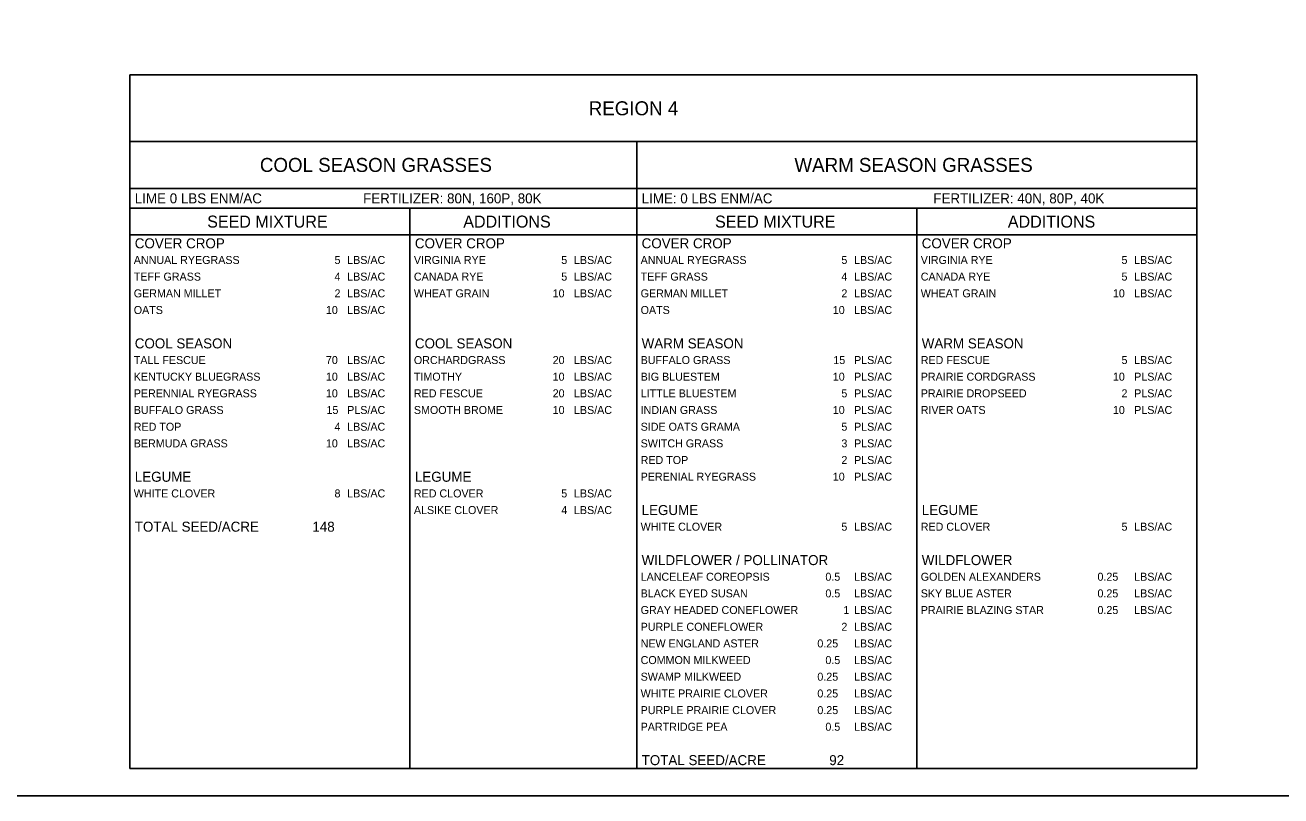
# Model space of a CAD drawing. Extents: x 0 to 3125, y 0 to 2037.
# Drawn here: x 1074 to 2214, y 0 to 699 of the extents above; entities that cross this region are included whole.
import ezdxf

# ---------------------------------------------------------------- set-up
doc = ezdxf.new("R2010")
doc.units = 0
for name, color, linetype in [('Common-Notes', 7, 'Continuous'), ('Draft_Named_Boundary', 7, 'Continuous'), ('Grid_Line-Main', 7, 'Continuous')]:
    doc.layers.add(name, color=color, linetype=linetype)

msp = doc.modelspace()

# ---------------------------------------------------------------- linework, layer by layer
at = {"layer": 'Draft_Named_Boundary'}
msp.add_lwpolyline([(0, 0), (3125, 0), (3125, 2037.5), (0, 2037.5)], close=True, dxfattribs=at)
at = {"layer": 'Grid_Line-Main'}
for p, q in [((1169.4, 654.1), (2137.4, 654.1)), ((1169.4, 654.1), (1169.4, 24.9)), ((2137.4, 654.1), (2137.4, 24.9)), ((1169.4, 593.6), (2137.4, 593.6)), ((1629.2, 593.6), (1629.2, 24.9)), ((1169.4, 551.2), (2137.4, 551.2)), ((1169.4, 533.1), (2137.4, 533.1)), ((1423.5, 533.1), (1423.5, 24.9)), ((1883.3, 533.1), (1883.3, 24.9)), ((1169.4, 508.9), (2137.4, 508.9)), ((1169.4, 24.9), (2137.4, 24.9))]:
    msp.add_line(p, q, dxfattribs=at)

# ---------------------------------------------------------------- texts
at = {"layer": 'Common-Notes'}
for s, height, p in [(' REGION 4', 12.7, (1581, 617.5)), ('COOL SEASON GRASSES', 12.705, (1287.4, 566.1)), ('WARM SEASON GRASSES', 12.705, (1772.3, 566.1)), ('LIME 0 LBS ENM/AC', 9.075, (1173.9, 537.6)), ('FERTILIZER: 80N, 160P, 80K', 9.075, (1381, 537.6)), ('LIME: 0 LBS ENM/AC', 9.075, (1633.7, 537.6)), ('FERTILIZER: 40N, 80P, 40K', 9.075, (1898.3, 537.6)), ('SEED MIXTURE', 10.89, (1239.6, 515.6)), ('ADDITIONS ', 10.89, (1471.9, 515.6)), ('SEED MIXTURE', 10.89, (1700.3, 515.6)), ('ADDITIONS ', 10.89, (1965.9, 515.6)), ('COVER CROP', 9.08, (1173.9, 496.8)), ('COVER CROP', 9.08, (1428, 496.8)), ('COVER CROP', 9.08, (1633.7, 496.8)), ('COVER CROP', 9.08, (1887.8, 496.8)), ('ANNUAL RYEGRASS', 7.26, (1173, 482.6)), ('5', 7.26, (1355.1, 482.6)), ('LBS/AC', 7.26, (1366.6, 482.6)), ('VIRGINIA RYE', 7.26, (1427.1, 482.6)), ('5', 7.26, (1560.8, 482.6)), ('LBS/AC', 7.26, (1572.3, 482.6)), ('ANNUAL RYEGRASS', 7.26, (1632.8, 482.6)), ('5', 7.26, (1814.9, 482.6)), ('LBS/AC', 7.26, (1826.4, 482.6)), ('VIRGINIA RYE', 7.26, (1886.9, 482.6)), ('5', 7.26, (2069, 482.6)), ('LBS/AC', 7.26, (2080.5, 482.6)), ('TEFF GRASS', 7.26, (1173, 467.5)), ('4', 7.26, (1355.1, 467.5)), ('LBS/AC', 7.26, (1366.6, 467.5)), ('CANADA RYE', 7.26, (1427.1, 467.5)), ('5', 7.26, (1560.8, 467.5)), ('LBS/AC', 7.26, (1572.3, 467.5)), ('TEFF GRASS', 7.26, (1632.8, 467.5)), ('4', 7.26, (1814.9, 467.5)), ('LBS/AC', 7.26, (1826.4, 467.5)), ('CANADA RYE', 7.26, (1886.9, 467.5)), ('5', 7.26, (2069, 467.5)), ('LBS/AC', 7.26, (2080.5, 467.5)), ('GERMAN MILLET', 7.26, (1173, 452.3)), ('2', 7.26, (1355.1, 452.3)), ('LBS/AC', 7.26, (1366.6, 452.3)), ('WHEAT GRAIN', 7.26, (1427.1, 452.3)), ('10', 7.26, (1553, 452.3)), ('LBS/AC', 7.26, (1572.3, 452.3)), ('GERMAN MILLET', 7.26, (1632.8, 452.3)), ('2', 7.26, (1814.9, 452.3)), ('LBS/AC', 7.26, (1826.4, 452.3)), ('WHEAT GRAIN', 7.26, (1886.9, 452.3)), ('10', 7.26, (2061.2, 452.3)), ('LBS/AC', 7.26, (2080.5, 452.3)), ('OATS', 7.26, (1173, 437.2)), ('10', 7.26, (1347.3, 437.2)), ('LBS/AC', 7.26, (1366.6, 437.2)), ('OATS', 7.26, (1632.8, 437.2)), ('10', 7.26, (1807.1, 437.2)), ('LBS/AC', 7.26, (1826.4, 437.2)), ('COOL SEASON', 9.075, (1173.9, 406)), ('COOL SEASON', 9.075, (1428, 406)), ('WARM SEASON', 9.075, (1633.7, 406)), ('WARM SEASON', 9.075, (1887.8, 406)), ('TALL FESCUE', 7.26, (1173, 391.8)), ('70', 7.26, (1347.3, 391.8)), ('LBS/AC', 7.26, (1366.6, 391.8)), ('ORCHARDGRASS', 7.26, (1427.1, 391.8)), ('20', 7.26, (1553, 391.8)), ('LBS/AC', 7.26, (1572.3, 391.8)), ('BUFFALO GRASS', 7.26, (1632.8, 391.8)), ('15', 7.26, (1807.6, 391.8)), ('PLS/AC', 7.26, (1826.4, 391.8)), ('RED FESCUE', 7.26, (1886.9, 391.8)), ('5', 7.26, (2069, 391.8)), ('LBS/AC', 7.26, (2080.5, 391.8)), ('KENTUCKY BLUEGRASS', 7.26, (1173, 376.7)), ('10', 7.26, (1347.3, 376.7)), ('LBS/AC', 7.26, (1366.6, 376.7)), ('TIMOTHY', 7.26, (1427.1, 376.7)), ('10', 7.26, (1553, 376.7)), ('LBS/AC', 7.26, (1572.3, 376.7)), ('BIG BLUESTEM', 7.26, (1632.8, 376.7)), ('10', 7.26, (1807.1, 376.7)), ('PLS/AC', 7.26, (1826.4, 376.7)), ('PRAIRIE CORDGRASS', 7.26, (1886.9, 376.7)), ('10', 7.26, (2061.2, 376.7)), ('PLS/AC', 7.26, (2080.5, 376.7)), ('PERENNIAL RYEGRASS', 7.26, (1173, 361.6)), ('10', 7.26, (1347.3, 361.6)), ('LBS/AC', 7.26, (1366.6, 361.6)), ('RED FESCUE', 7.26, (1427.1, 361.6)), ('20', 7.26, (1553, 361.6)), ('LBS/AC', 7.26, (1572.3, 361.6)), ('LITTLE BLUESTEM', 7.26, (1632.8, 361.6)), ('5', 7.26, (1814.9, 361.6)), ('PLS/AC', 7.26, (1826.4, 361.6)), ('PRAIRIE DROPSEED', 7.26, (1886.9, 361.6)), ('2', 7.26, (2069, 361.6)), ('PLS/AC', 7.26, (2080.5, 361.6)), ('BUFFALO GRASS', 7.26, (1173, 346.5)), ('15', 7.26, (1347.8, 346.5)), ('PLS/AC', 7.26, (1366.6, 346.5)), ('SMOOTH BROME', 7.26, (1427.1, 346.5)), ('10', 7.26, (1553, 346.5)), ('LBS/AC', 7.26, (1572.3, 346.5)), ('INDIAN GRASS', 7.26, (1632.8, 346.5)), ('10', 7.26, (1807.1, 346.5)), ('PLS/AC', 7.26, (1826.4, 346.5)), ('RIVER OATS', 7.26, (1886.9, 346.5)), ('10', 7.26, (2061.2, 346.5)), ('PLS/AC', 7.26, (2080.5, 346.5)), ('RED TOP', 7.26, (1173, 331.3)), ('4', 7.26, (1355.1, 331.3)), ('LBS/AC', 7.26, (1366.6, 331.3)), ('SIDE OATS GRAMA', 7.26, (1632.8, 331.3)), ('5', 7.26, (1814.9, 331.3)), ('PLS/AC', 7.26, (1826.4, 331.3)), ('BERMUDA GRASS', 7.26, (1173, 316.2)), ('10', 7.26, (1347.3, 316.2)), ('LBS/AC', 7.26, (1366.6, 316.2)), ('SWITCH GRASS', 7.26, (1632.8, 316.2)), ('3', 7.26, (1814.9, 316.2)), ('PLS/AC', 7.26, (1826.4, 316.2)), ('RED TOP', 7.26, (1632.8, 301.1)), ('2', 7.26, (1814.9, 301.1)), ('PLS/AC', 7.26, (1826.4, 301.1)), ('LEGUME', 9.08, (1173.9, 285)), ('LEGUME', 9.08, (1428, 285)), ('PERENIAL RYEGRASS', 7.26, (1632.8, 286)), ('10', 7.26, (1807.1, 286)), ('PLS/AC', 7.26, (1826.4, 286)), ('WHITE CLOVER', 7.26, (1173, 270.8)), ('8', 7.26, (1355.1, 270.8)), ('LBS/AC', 7.26, (1366.6, 270.8)), ('RED CLOVER', 7.26, (1427.1, 270.8)), ('5', 7.26, (1560.8, 270.8)), ('LBS/AC', 7.26, (1572.3, 270.8)), ('ALSIKE CLOVER', 7.26, (1427.1, 255.7)), ('4', 7.26, (1560.8, 255.7)), ('LBS/AC', 7.26, (1572.3, 255.7)), ('LEGUME ', 9.08, (1633.7, 254.8)), ('LEGUME', 9.08, (1887.8, 254.8)), ('TOTAL SEED/ACRE', 9.075, (1173.9, 239.7)), ('148', 9.08, (1335, 239.7)), ('WHITE CLOVER', 7.26, (1632.8, 240.6)), ('5', 7.26, (1814.9, 240.6)), ('LBS/AC', 7.26, (1826.4, 240.6)), ('RED CLOVER', 7.26, (1886.9, 240.6)), ('5', 7.26, (2069, 240.6)), ('LBS/AC', 7.26, (2080.5, 240.6)), ('WILDFLOWER / POLLINATOR ', 9.075, (1633.7, 209.4)), ('WILDFLOWER', 9.08, (1887.8, 209.4)), ('LANCELEAF COREOPSIS', 7.26, (1632.8, 195.2)), ('0.5', 7.26, (1800.4, 195.2)), ('LBS/AC', 7.26, (1826.4, 195.2)), ('GOLDEN ALEXANDERS', 7.26, (1886.9, 195.2)), ('0.25', 7.26, (2047.2, 195.2)), ('LBS/AC', 7.26, (2080.5, 195.2)), ('BLACK EYED SUSAN', 7.26, (1632.8, 180.1)), ('0.5', 7.26, (1800.4, 180.1)), ('LBS/AC', 7.26, (1826.4, 180.1)), ('SKY BLUE ASTER', 7.26, (1886.9, 180.1)), ('0.25', 7.26, (2047.2, 180.1)), ('LBS/AC', 7.26, (2080.5, 180.1)), ('GRAY HEADED CONEFLOWER', 7.26, (1632.8, 165)), ('1', 7.26, (1816.7, 165)), ('LBS/AC', 7.26, (1826.4, 165)), ('PRAIRIE BLAZING STAR', 7.26, (1886.9, 165)), ('0.25', 7.26, (2047.2, 165)), ('LBS/AC', 7.26, (2080.5, 165)), ('PURPLE CONEFLOWER', 7.26, (1632.8, 149.8)), ('2', 7.26, (1814.9, 149.8)), ('LBS/AC', 7.26, (1826.4, 149.8)), ('NEW ENGLAND ASTER', 7.26, (1632.8, 134.7)), ('0.25', 7.26, (1793.1, 134.7)), ('LBS/AC', 7.26, (1826.4, 134.7)), ('COMMON MILKWEED', 7.26, (1632.8, 119.6)), ('0.5', 7.26, (1800.4, 119.6)), ('LBS/AC', 7.26, (1826.4, 119.6)), ('SWAMP MILKWEED', 7.26, (1632.8, 104.5)), ('0.25', 7.26, (1793.1, 104.5)), ('LBS/AC', 7.26, (1826.4, 104.5)), ('WHITE PRAIRIE CLOVER', 7.26, (1632.8, 89.3)), ('0.25', 7.26, (1793.1, 89.3)), ('LBS/AC', 7.26, (1826.4, 89.3)), ('PURPLE PRAIRIE CLOVER', 7.26, (1632.8, 74.2)), ('0.25', 7.26, (1793.1, 74.2)), ('LBS/AC', 7.26, (1826.4, 74.2)), ('PARTRIDGE PEA', 7.26, (1632.8, 59.1)), ('0.5', 7.26, (1800.4, 59.1)), ('LBS/AC', 7.26, (1826.4, 59.1)), ('TOTAL SEED/ACRE', 9.075, (1633.7, 27.9)), ('92', 9.08, (1803.9, 27.9))]:
    msp.add_text(s, height=height, dxfattribs=at).set_placement(p)

doc.saveas('drawing.dxf')
